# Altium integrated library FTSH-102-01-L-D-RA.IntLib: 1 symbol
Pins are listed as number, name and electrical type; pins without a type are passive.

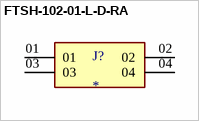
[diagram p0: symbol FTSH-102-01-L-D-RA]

## FTSH-102-01-L-D-RA
designator J?
MF: Samtec Inc.; MP: FTSH-102-01-L-D-RA
footprint SAMTEC_FTSH-102-01-L-D-RA
pins: 01, 02, 03, 04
